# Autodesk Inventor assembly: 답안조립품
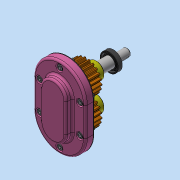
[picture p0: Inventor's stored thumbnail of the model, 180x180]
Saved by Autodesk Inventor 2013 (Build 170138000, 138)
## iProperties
Created: 2020-09
Part Number: 답안조립품
Document SubType Name: Assembly
Designer: Administrator
Author: Administrator
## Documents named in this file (11)
- C:\Users\Administrator\Desktop\700906V1042\답안조립품.iam
- C:\Users\Administrator\Desktop\700906V1042\본체.ipt
- C:\Users\Administrator\Desktop\700906V1042\베어링부시.ipt
- C:\Users\Administrator\Desktop\700906V1042\커버.ipt
- C:\Users\Administrator\Desktop\700906V1042\볼트 M5.ipt
- C:\Users\Administrator\Desktop\700906V1042\메인축.ipt
- C:\Users\Administrator\Desktop\700906V1042\서브축.ipt
- C:\Users\Administrator\Desktop\700906V1042\오일 실 16 28 7.ipt
- C:\Users\Administrator\Desktop\700906V1042\키 6 x 6 x 18.ipt
- C:\Users\Administrator\Desktop\700906V1042\스퍼기어.ipt
- C:\Users\Administrator\Desktop\700906V1042\개스킷.ipt
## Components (1 placed, 1 different names)
1. 개스킷:1
